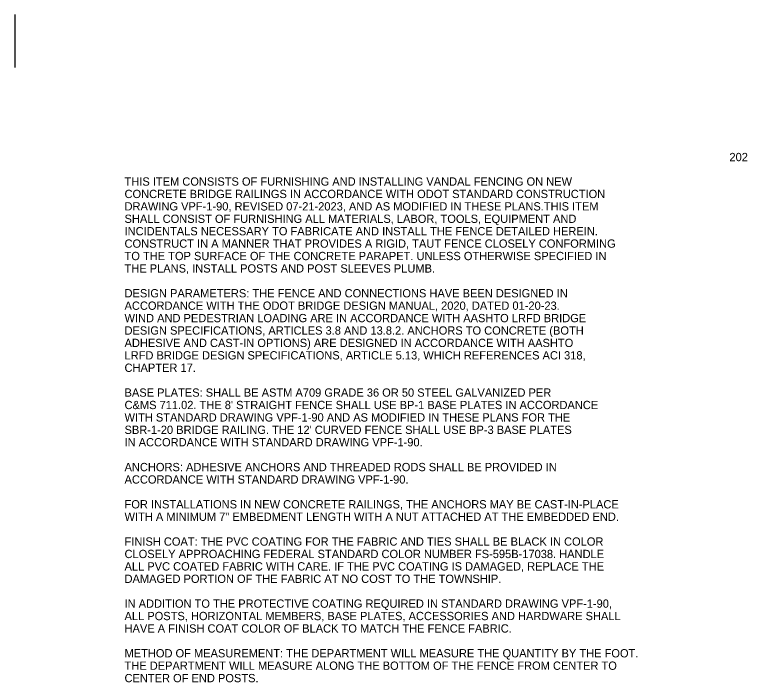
# Model space of a CAD drawing. Extents: x -70 to 76, y -5 to 22.
# Drawn here: x 39.12 to 51.52, y 7.13 to 18.43 of the extents above; entities that cross this region are included whole.
import ezdxf

# ---------------------------------------------------------------- set-up
doc = ezdxf.new("R2010")
doc.units = 0
doc.layers.add('BR_P_Gen_Text', color=7, linetype='Continuous')

msp = doc.modelspace()

# ---------------------------------------------------------------- linework, layer by layer
at = {"layer": 'BR_P_Gen_Text'}
for p, q in [((39.122, 18.429), (39.122, 17.957)), ((39.122, 17.957), (39.122, 17.537))]:
    msp.add_line(p, q, dxfattribs=at)

# ---------------------------------------------------------------- texts
for s, p in [('202', (51.217, 15.95)), ('THIS ITEM CONSISTS OF FURNISHING AND INSTALLING VANDAL FENCING ON NEW ', (40.981, 15.536)), ('CONCRETE BRIDGE RAILINGS IN ACCORDANCE WITH ODOT STANDARD CONSTRUCTION ', (40.981, 15.326)), ('DRAWING VPF-1-90, REVISED 07-21-2023, AND AS MODIFIED IN THESE PLANS.THIS ITEM ', (40.981, 15.116)), ('SHALL CONSIST OF FURNISHING ALL MATERIALS, LABOR, TOOLS, EQUIPMENT AND ', (40.981, 14.906)), ('INCIDENTALS NECESSARY TO FABRICATE AND INSTALL THE FENCE DETAILED HEREIN. ', (40.981, 14.696)), ('CONSTRUCT IN A MANNER THAT PROVIDES A RIGID, TAUT FENCE CLOSELY CONFORMING ', (40.981, 14.486)), ('TO THE TOP SURFACE OF THE CONCRETE PARAPET. UNLESS OTHERWISE SPECIFIED IN ', (40.981, 14.276)), ('THE PLANS, INSTALL POSTS AND POST SLEEVES PLUMB.', (40.981, 14.066)), ('DESIGN PARAMETERS: THE FENCE AND CONNECTIONS HAVE BEEN DESIGNED IN ', (40.981, 13.646)), ('ACCORDANCE WITH THE ODOT BRIDGE DESIGN MANUAL, 2020, DATED 01-20-23. ', (40.981, 13.436)), ('WIND AND PEDESTRIAN LOADING ARE IN ACCORDANCE WITH AASHTO LRFD BRIDGE ', (40.981, 13.226)), ('DESIGN SPECIFICATIONS, ARTICLES 3.8 AND 13.8.2. ANCHORS TO CONCRETE (BOTH ', (40.981, 13.016)), ('ADHESIVE AND CAST-IN OPTIONS) ARE DESIGNED IN ACCORDANCE WITH AASHTO ', (40.981, 12.806)), ('LRFD BRIDGE DESIGN SPECIFICATIONS, ARTICLE 5.13, WHICH REFERENCES ACI 318, ', (40.981, 12.596)), ('CHAPTER 17. ', (40.981, 12.386)), ('BASE PLATES: SHALL BE ASTM A709 GRADE 36 OR 50 STEEL GALVANIZED PER ', (40.981, 11.966)), ("C&MS 711.02. THE 8' STRAIGHT FENCE SHALL USE BP-1 BASE PLATES IN ACCORDANCE", (40.981, 11.756)), ('WITH STANDARD DRAWING VPF-1-90 AND AS MODIFIED IN THESE PLANS FOR THE ', (40.981, 11.546)), ("SBR-1-20 BRIDGE RAILING. THE 12' CURVED FENCE SHALL USE BP-3 BASE PLATES", (40.981, 11.336)), ('IN ACCORDANCE WITH STANDARD DRAWING VPF-1-90.', (40.981, 11.126)), ('ANCHORS: ADHESIVE ANCHORS AND THREADED RODS SHALL BE PROVIDED IN ', (40.981, 10.706)), ('ACCORDANCE WITH STANDARD DRAWING VPF-1-90.', (40.981, 10.496)), ('FOR INSTALLATIONS IN NEW CONCRETE RAILINGS, THE ANCHORS MAY BE CAST-IN-PLACE', (40.981, 10.076)), ('WITH A MINIMUM 7" EMBEDMENT LENGTH WITH A NUT ATTACHED AT THE EMBEDDED END.', (40.981, 9.866)), ('FINISH COAT: THE PVC COATING FOR THE FABRIC AND TIES SHALL BE BLACK IN COLOR ', (40.981, 9.446)), ('CLOSELY APPROACHING FEDERAL STANDARD COLOR NUMBER FS-595B-17038. HANDLE ', (40.981, 9.236)), ('ALL PVC COATED FABRIC WITH CARE. IF THE PVC COATING IS DAMAGED, REPLACE THE ', (40.981, 9.026)), ('DAMAGED PORTION OF THE FABRIC AT NO COST TO THE TOWNSHIP.', (40.981, 8.816)), ('IN ADDITION TO THE PROTECTIVE COATING REQUIRED IN STANDARD DRAWING VPF-1-90, ', (40.981, 8.396)), ('ALL POSTS, HORIZONTAL MEMBERS, BASE PLATES, ACCESSORIES AND HARDWARE SHALL ', (40.981, 8.186)), ('HAVE A FINISH COAT COLOR OF BLACK TO MATCH THE FENCE FABRIC. ', (40.981, 7.976)), ('METHOD OF MEASUREMENT: THE DEPARTMENT WILL MEASURE THE QUANTITY BY THE FOOT. ', (40.981, 7.556)), ('THE DEPARTMENT WILL MEASURE ALONG THE BOTTOM OF THE FENCE FROM CENTER TO ', (40.981, 7.346)), ('CENTER OF END POSTS.', (40.981, 7.136))]:
    msp.add_text(s, height=0.14, dxfattribs=at).set_placement(p)

doc.saveas('drawing.dxf')
